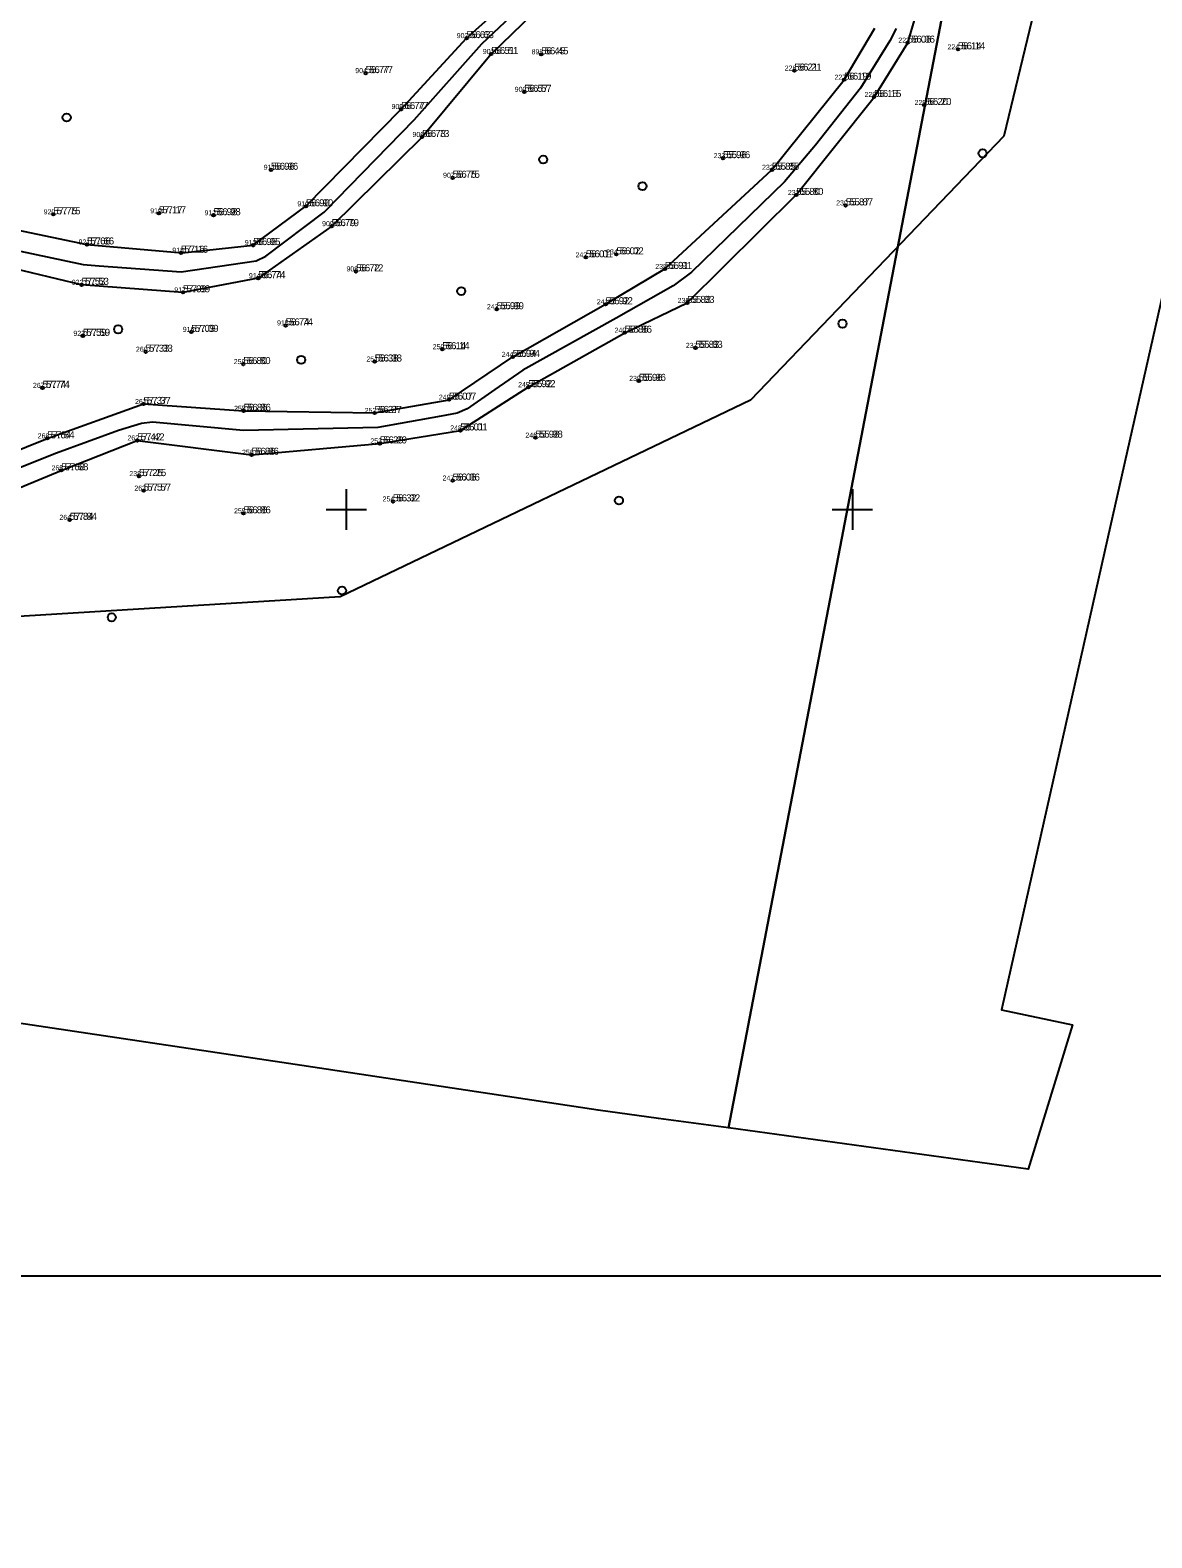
# Model space of a CAD drawing. Extents: x 554846 to 556995, y 6445875 to 6446723.
# Drawn here: x 555368.8 to 555479.6, y 6445948.4 to 6446097.4 of the extents above; entities that cross this region are included whole.
import ezdxf

# ---------------------------------------------------------------- set-up
doc = ezdxf.new("R2010")
doc.units = 0
for name, color, linetype in [('HALJASTUS', 7, 'Continuous'), ('KORGUS-EH2000', 7, 'Continuous'), ('MOOTKORG-EH2000', 7, 'Continuous'), ('MOOTMPUNKT', 7, 'Continuous'), ('MOOTNR', 7, 'Continuous'), ('MOOTPIIR', 7, 'Continuous'), ('PIIR', 7, 'Continuous'), ('TEE', 7, 'Continuous'), ('VORK', 7, 'Continuous'), ('VORMISTUS', 7, 'Continuous')]:
    doc.layers.add(name, color=color, linetype=linetype)

msp = doc.modelspace()

# ---------------------------------------------------------------- linework, layer by layer
at = {"layer": 'HALJASTUS'}
for centre in [(555372.37, 6446088.73), (555419.46, 6446084.58), (555462.87, 6446085.2), (555429.26, 6446081.95), (555411.36, 6446071.58), (555449.03, 6446068.37), (555377.46, 6446067.81), (555395.54, 6446064.79), (555426.94, 6446050.89), (555399.58, 6446041.99), (555376.83, 6446039.35)]:
    msp.add_circle(centre, 0.4, dxfattribs=at)
at = {"layer": 'KORGUS-EH2000'}
for centre in [(555411.89, 6446096.58), (555455.47, 6446096.13), (555460.43, 6446095.47), (555414.31, 6446095.01), (555419.26, 6446094.98), (555401.92, 6446093.12), (555444.27, 6446093.37), (555449.19, 6446092.47), (555417.59, 6446091.27), (555452.15, 6446090.76), (555405.42, 6446089.57), (555457.1, 6446089.97), (555407.49, 6446086.81), (555437.22, 6446084.72), (555392.56, 6446083.57), (555442.06, 6446083.57), (555410.51, 6446082.78), (555444.45, 6446081.08), (555371.05, 6446079.17), (555381.48, 6446079.27), (555386.88, 6446079.08), (555396.02, 6446079.96), (555449.35, 6446080.05), (555398.56, 6446078), (555374.38, 6446076.19), (555390.8, 6446076.13), (555383.66, 6446075.37), (555423.67, 6446074.92), (555426.69, 6446075.21), (555391.3, 6446072.86), (555400.97, 6446073.53), (555431.48, 6446073.77), (555373.85, 6446072.2), (555383.86, 6446071.46), (555414.86, 6446069.79), (555425.62, 6446070.28), (555433.69, 6446070.41), (555373.97, 6446067.16), (555384.69, 6446067.55), (555394.01, 6446068.19), (555427.51, 6446067.47), (555380.17, 6446065.59), (555409.49, 6446065.84), (555434.5, 6446065.97), (555389.83, 6446064.37), (555402.81, 6446064.62), (555416.44, 6446065.08), (555428.9, 6446062.71), (555369.99, 6446062.02), (555417.98, 6446062.09), (555379.96, 6446060.43), (555389.86, 6446059.75), (555389.86, 6446059.75), (555402.8, 6446059.54), (555410.15, 6446060.85), (555370.46, 6446057.03), (555379.35, 6446056.83), (555403.31, 6446056.53), (555411.27, 6446057.81), (555418.7, 6446057.1), (555390.65, 6446055.41), (555371.83, 6446053.87), (555379.52, 6446053.3), (555410.51, 6446052.86), (555379.99, 6446051.86), (555404.61, 6446050.8), (555372.68, 6446048.98), (555389.85, 6446049.62)]:
    msp.add_circle(centre, 0.125, dxfattribs=at)
at = {"layer": 'MOOTMPUNKT'}
for centre in [(555411.89, 6446096.58), (555455.47, 6446096.13), (555460.43, 6446095.47), (555414.31, 6446095.01), (555419.26, 6446094.98), (555401.92, 6446093.12), (555444.27, 6446093.37), (555449.19, 6446092.47), (555417.59, 6446091.27), (555452.15, 6446090.76), (555405.42, 6446089.57), (555457.1, 6446089.97), (555407.49, 6446086.81), (555437.22, 6446084.72), (555392.56, 6446083.57), (555442.06, 6446083.57), (555410.51, 6446082.78), (555444.45, 6446081.08), (555371.05, 6446079.17), (555381.48, 6446079.27), (555386.88, 6446079.08), (555396.02, 6446079.96), (555449.35, 6446080.05), (555398.56, 6446078), (555374.38, 6446076.19), (555390.8, 6446076.13), (555383.66, 6446075.37), (555423.67, 6446074.92), (555426.69, 6446075.21), (555391.3, 6446072.86), (555400.97, 6446073.53), (555431.48, 6446073.77), (555373.85, 6446072.2), (555383.86, 6446071.46), (555414.86, 6446069.79), (555425.62, 6446070.28), (555433.69, 6446070.41), (555373.97, 6446067.16), (555384.69, 6446067.55), (555394.01, 6446068.19), (555427.51, 6446067.47), (555380.17, 6446065.59), (555409.49, 6446065.84), (555434.5, 6446065.97), (555389.83, 6446064.37), (555402.81, 6446064.62), (555416.44, 6446065.08), (555428.9, 6446062.71), (555369.99, 6446062.02), (555417.98, 6446062.09), (555379.96, 6446060.43), (555389.86, 6446059.75), (555389.86, 6446059.75), (555402.8, 6446059.54), (555410.15, 6446060.85), (555370.46, 6446057.03), (555379.35, 6446056.83), (555403.31, 6446056.53), (555411.27, 6446057.81), (555418.7, 6446057.1), (555390.65, 6446055.41), (555371.83, 6446053.87), (555379.52, 6446053.3), (555410.51, 6446052.86), (555379.99, 6446051.86), (555404.61, 6446050.8), (555372.68, 6446048.98), (555389.85, 6446049.62)]:
    msp.add_circle(centre, 0.125, dxfattribs=at)
at = {"layer": 'MOOTPIIR'}
msp.add_lwpolyline([(555856.56, 6446356.05), (555752.84, 6446263.06), (555653.54, 6446239.26), (555594.53, 6446196.06), (555554.98, 6446185.17), (555476.19, 6446171.98), (555473.22, 6446121.18), (555464.98, 6446086.88), (555439.93, 6446060.82), (555399.38, 6446041.36), (555318.62, 6446036.42), (555233.24, 6446050.27)], dxfattribs=at)
at = {"layer": 'PIIR'}
msp.add_lwpolyline([(555848.15, 6446270.05), (555770.44, 6446257.1), (555601.76, 6446236.19), (555592.08, 6446205.8), (555590.17, 6446199.81), (555547.72, 6446198.88), (555471.93, 6446166.68), (555437.75, 6445988.89), (555430.84, 6445989.84), (555424.9, 6445990.66), (555394.94, 6445995.15), (555348.46, 6446002.11), (555303.97, 6446008.78), (555290.27, 6445950.91), (555289.66, 6445948.39), (555259.76, 6445985.47)], dxfattribs=at)
msp.add_lwpolyline([(555594.35, 6446199.31), (555580.72, 6446194.53), (555573.2, 6446192.45), (555562.73, 6446139.8), (555499.33, 6446154.09), (555491.55, 6446119.62), (555486.57, 6446097.52), (555481.82, 6446076.44), (555475.25, 6446047.27), (555464.73, 6446000.58), (555471.74, 6445999.08), (555467.38, 6445984.82), (555437.75, 6445988.89), (555471.93, 6446166.68), (555547.72, 6446198.88), (555590.17, 6446199.81)], close=True, dxfattribs=at)
at = {"layer": 'TEE'}
for points in [[(555256.61, 6446082.39), (555267.96, 6446080.12), (555279.72, 6446079.09), (555291.51, 6446080.24), (555300.12, 6446082.08), (555312.15, 6446084.79), (555319.08, 6446084.59), (555325.91, 6446083.6), (555336.42, 6446083), (555348.87, 6446084.02), (555357.05, 6446080.92), (555364.6, 6446078.23), (555374.38, 6446076.19), (555383.78, 6446075.37), (555390.8, 6446076.13), (555396.02, 6446079.96), (555405.42, 6446089.57), (555411.89, 6446096.58), (555419.56, 6446103.46)], [(555362.59, 6446050.02), (555371.83, 6446053.87), (555379.35, 6446056.83), (555390.65, 6446055.41), (555403.31, 6446056.53), (555411.27, 6446057.81), (555417.98, 6446062.09), (555427.51, 6446067.47), (555433.69, 6446070.41), (555444.45, 6446081.08), (555452.15, 6446090.76), (555455.47, 6446096.13), (555457.38, 6446102.63)], [(555419.45, 6446099.97), (555414.31, 6446095.01), (555407.49, 6446086.81), (555398.56, 6446078), (555391.3, 6446072.86), (555383.86, 6446071.46), (555373.85, 6446072.2), (555363.92, 6446074.58), (555356.22, 6446077.48), (555347.89, 6446080.29), (555336.39, 6446079.7), (555324.93, 6446080.84), (555318.7, 6446081.51), (555311.81, 6446081.32), (555301.28, 6446078.68), (555291.5, 6446076.78), (555279.92, 6446075.3), (555267.57, 6446076.5), (555255.14, 6446078.33)], [(555365.8, 6446075.96), (555374.01, 6446074.2), (555375.6, 6446074.08), (555383.67, 6446073.48), (555391.11, 6446074.58), (555392.06, 6446075.04), (555397.81, 6446079.38), (555406.7, 6446088.52), (555413.39, 6446096.01), (555418.56, 6446100.94)], [(555260.14, 6446058.52), (555267.45, 6446056.62), (555271.68, 6446055.36), (555278.75, 6446053.22), (555289.07, 6446052.56), (555303.18, 6446049.3), (555306.24, 6446048.9), (555313.8, 6446049.13), (555323.86, 6446049.99), (555333.31, 6446049.62), (555338.67, 6446048.65), (555345.24, 6446049.45), (555362.23, 6446053.72), (555370.46, 6446057.03), (555379.96, 6446060.43), (555389.86, 6446059.75), (555402.8, 6446059.54), (555410.15, 6446060.85), (555416.44, 6446065.08), (555425.62, 6446070.28), (555431.48, 6446073.77), (555442.06, 6446083.57), (555449.19, 6446092.47), (555452.21, 6446097.57)], [(555454.33, 6446097.54), (555453.69, 6446096.32), (555450.82, 6446091.64), (555446.37, 6446086.01), (555443.31, 6446082.39), (555434.12, 6446073.45), (555432.31, 6446072.09), (555426.65, 6446068.92), (555417.43, 6446063.76), (555414.68, 6446061.85), (555411.94, 6446059.95), (555410.95, 6446059.51), (555409.39, 6446059.23), (555403.11, 6446058.09), (555389.85, 6446057.81), (555380.85, 6446058.64), (555379.76, 6446058.5), (555377.48, 6446057.81), (555371.37, 6446055.57), (555362.89, 6446052.22)]]:
    msp.add_lwpolyline(points, dxfattribs=at)
at = {"layer": 'VORK'}
for p, q in [((555400, 6446052), (555400, 6446048)), ((555450, 6446052), (555450, 6446048)), ((555398, 6446050), (555402, 6446050)), ((555448, 6446050), (555452, 6446050))]:
    msp.add_line(p, q, dxfattribs=at)
at = {"layer": 'VORMISTUS'}
msp.add_lwpolyline([(555573.73, 6445974.27), (555573.73, 6446387.77), (554994.23, 6446387.77), (554994.23, 6445974.27), (555573.73, 6445974.27)], dxfattribs=at)

# ---------------------------------------------------------------- texts
at = {"layer": 'KORGUS-EH2000'}
for s, p in [('56.63', (555412.24, 6446096.58)), ('56.06', (555455.82, 6446096.13)), ('56.51', (555414.66, 6446095.01)), ('56.45', (555419.61, 6446094.98)), ('56.14', (555460.78, 6446095.47)), ('56.77', (555402.27, 6446093.12)), ('56.21', (555444.62, 6446093.37)), ('56.19', (555449.54, 6446092.47)), ('56.57', (555417.94, 6446091.27)), ('56.15', (555452.5, 6446090.76)), ('56.77', (555405.77, 6446089.57)), ('56.20', (555457.45, 6446089.97)), ('56.73', (555407.84, 6446086.81)), ('55.96', (555437.57, 6446084.72)), ('56.96', (555392.91, 6446083.57)), ('56.75', (555410.86, 6446082.78)), ('55.85', (555442.41, 6446083.57)), ('56.90', (555396.37, 6446079.96)), ('55.80', (555444.8, 6446081.08)), ('55.87', (555449.7, 6446080.05)), ('57.75', (555371.4, 6446079.17)), ('57.17', (555381.83, 6446079.27)), ('56.98', (555387.23, 6446079.08)), ('56.79', (555398.91, 6446078)), ('57.66', (555374.72, 6446076.19)), ('57.16', (555384.01, 6446075.37)), ('56.95', (555391.15, 6446076.13)), ('56.02', (555427.04, 6446075.21)), ('56.01', (555424.02, 6446074.92)), ('55.91', (555431.83, 6446073.77)), ('57.53', (555374.2, 6446072.2)), ('56.74', (555391.65, 6446072.86)), ('56.72', (555401.32, 6446073.53)), ('57.09', (555384.21, 6446071.46)), ('55.99', (555415.21, 6446069.79)), ('55.92', (555425.97, 6446070.28)), ('55.83', (555434.04, 6446070.41)), ('56.74', (555394.36, 6446068.19)), ('57.59', (555374.32, 6446067.16)), ('57.09', (555385.04, 6446067.55)), ('55.86', (555427.86, 6446067.47)), ('57.33', (555380.52, 6446065.59)), ('56.14', (555409.84, 6446065.84)), ('55.94', (555416.79, 6446065.08)), ('55.83', (555434.85, 6446065.97)), ('56.80', (555390.18, 6446064.37)), ('56.38', (555403.16, 6446064.62)), ('57.74', (555370.34, 6446062.02)), ('55.92', (555418.33, 6446062.09)), ('55.96', (555429.24, 6446062.71)), ('57.37', (555380.31, 6446060.43)), ('56.07', (555410.5, 6446060.85)), ('56.86', (555390.21, 6446059.75)), ('56.86', (555390.21, 6446059.75)), ('56.27', (555403.15, 6446059.54)), ('56.01', (555411.62, 6446057.81)), ('57.64', (555370.81, 6446057.03)), ('57.42', (555379.7, 6446056.83)), ('56.29', (555403.66, 6446056.53)), ('55.98', (555419.05, 6446057.1)), ('56.86', (555391, 6446055.41)), ('57.68', (555372.18, 6446053.87)), ('57.25', (555379.87, 6446053.3)), ('56.06', (555410.86, 6446052.86)), ('57.57', (555380.34, 6446051.86)), ('56.32', (555404.96, 6446050.8)), ('57.84', (555373.03, 6446048.98)), ('56.86', (555390.2, 6446049.62))]:
    msp.add_text(s, height=0.7, dxfattribs=at).set_placement(p)
at = {"layer": 'MOOTKORG-EH2000'}
for s, p in [('56.63', (555411.89, 6446096.58)), ('56.06', (555455.47, 6446096.13)), ('56.51', (555414.31, 6446095.01)), ('56.45', (555419.26, 6446094.98)), ('56.14', (555460.43, 6446095.47)), ('56.77', (555401.92, 6446093.12)), ('56.21', (555444.27, 6446093.37)), ('56.19', (555449.19, 6446092.47)), ('56.57', (555417.59, 6446091.27)), ('56.15', (555452.15, 6446090.76)), ('56.77', (555405.42, 6446089.57)), ('56.20', (555457.1, 6446089.97)), ('56.73', (555407.49, 6446086.81)), ('55.96', (555437.22, 6446084.72)), ('56.96', (555392.56, 6446083.57)), ('56.75', (555410.51, 6446082.78)), ('55.85', (555442.06, 6446083.57)), ('56.90', (555396.02, 6446079.96)), ('55.80', (555444.45, 6446081.08)), ('55.87', (555449.35, 6446080.05)), ('57.75', (555371.05, 6446079.17)), ('57.17', (555381.48, 6446079.27)), ('56.98', (555386.88, 6446079.08)), ('56.79', (555398.56, 6446078)), ('57.66', (555374.38, 6446076.19)), ('57.16', (555383.66, 6446075.37)), ('56.95', (555390.8, 6446076.13)), ('56.02', (555426.69, 6446075.21)), ('56.01', (555423.67, 6446074.92)), ('55.91', (555431.48, 6446073.77)), ('57.53', (555373.85, 6446072.2)), ('56.74', (555391.3, 6446072.86)), ('56.72', (555400.97, 6446073.53)), ('57.09', (555383.86, 6446071.46)), ('55.99', (555414.86, 6446069.79)), ('55.92', (555425.62, 6446070.28)), ('55.83', (555433.69, 6446070.41)), ('56.74', (555394.01, 6446068.19)), ('57.59', (555373.97, 6446067.16)), ('57.09', (555384.69, 6446067.55)), ('55.86', (555427.51, 6446067.47)), ('57.33', (555380.17, 6446065.59)), ('56.14', (555409.49, 6446065.84)), ('55.94', (555416.44, 6446065.08)), ('55.83', (555434.5, 6446065.97)), ('56.80', (555389.83, 6446064.37)), ('56.38', (555402.81, 6446064.62)), ('57.74', (555369.99, 6446062.02)), ('55.92', (555417.98, 6446062.09)), ('55.96', (555428.9, 6446062.71)), ('57.37', (555379.96, 6446060.43)), ('56.07', (555410.15, 6446060.85)), ('56.86', (555389.86, 6446059.75)), ('56.86', (555389.86, 6446059.75)), ('56.27', (555402.8, 6446059.54)), ('56.01', (555411.27, 6446057.81)), ('57.64', (555370.46, 6446057.03)), ('57.42', (555379.35, 6446056.83)), ('56.29', (555403.31, 6446056.53)), ('55.98', (555418.7, 6446057.1)), ('56.86', (555390.65, 6446055.41)), ('57.68', (555371.83, 6446053.87)), ('57.25', (555379.52, 6446053.3)), ('56.06', (555410.51, 6446052.86)), ('57.57', (555379.99, 6446051.86)), ('56.32', (555404.61, 6446050.8)), ('57.84', (555372.68, 6446048.98)), ('56.86', (555389.85, 6446049.62))]:
    msp.add_text(s, height=0.7, dxfattribs=at).set_placement(p)
at = {"layer": 'MOOTNR'}
for s, p in [('902', (555410.91, 6446096.58)), ('901', (555413.49, 6446095.01)), ('895', (555418.31, 6446094.98)), ('223', (555454.54, 6446096.13)), ('224', (555459.4, 6446095.47)), ('226', (555443.32, 6446093.37)), ('904', (555400.89, 6446093.12)), ('227', (555448.24, 6446092.47)), ('900', (555416.64, 6446091.27)), ('228', (555451.2, 6446090.76)), ('905', (555404.47, 6446089.57)), ('229', (555456.15, 6446089.97)), ('906', (555406.54, 6446086.81)), ('233', (555436.3, 6446084.72)), ('911', (555391.84, 6446083.57)), ('232', (555441.08, 6446083.57)), ('907', (555409.56, 6446082.78)), ('910', (555395.17, 6446079.96)), ('231', (555443.63, 6446081.08)), ('230', (555448.4, 6446080.05)), ('920', (555370.1, 6446079.17)), ('919', (555380.63, 6446079.27)), ('912', (555386, 6446079.08)), ('909', (555397.61, 6446078)), ('921', (555373.55, 6446076.19)), ('913', (555389.97, 6446076.13)), ('918', (555382.81, 6446075.37)), ('242', (555422.65, 6446074.92)), ('234', (555425.67, 6446075.21)), ('914', (555390.38, 6446072.86)), ('908', (555400.02, 6446073.53)), ('235', (555430.53, 6446073.77)), ('922', (555372.88, 6446072.2)), ('917', (555383.01, 6446071.46)), ('243', (555413.89, 6446069.79)), ('241', (555424.75, 6446070.28)), ('236', (555432.74, 6446070.41)), ('5', (555433.5, 6446070.34)), ('915', (555393.16, 6446068.19)), ('923', (555373.04, 6446067.16)), ('916', (555383.84, 6446067.55)), ('240', (555426.51, 6446067.47)), ('260', (555379.22, 6446065.59)), ('250', (555408.54, 6446065.84)), ('244', (555415.36, 6446065.08)), ('237', (555433.55, 6446065.97)), ('259', (555388.88, 6446064.37)), ('251', (555401.99, 6446064.62)), ('267', (555369.04, 6446062.02)), ('245', (555416.98, 6446062.09)), ('239', (555427.95, 6446062.71)), ('249', (555409.15, 6446060.85)), ('261', (555379.13, 6446060.43)), ('258', (555388.91, 6446059.75)), ('257', (555388.92, 6446059.75)), ('252', (555401.82, 6446059.54)), ('248', (555410.27, 6446057.81)), ('266', (555369.51, 6446057.03)), ('262', (555378.38, 6446056.83)), ('253', (555402.38, 6446056.53)), ('246', (555417.7, 6446057.1)), ('256', (555389.7, 6446055.41)), ('265', (555370.88, 6446053.87)), ('238', (555378.57, 6446053.3)), ('263', (555379.06, 6446051.86)), ('247', (555409.51, 6446052.86)), ('254', (555403.59, 6446050.8)), ('264', (555371.66, 6446048.98)), ('255', (555388.91, 6446049.62))]:
    msp.add_text(s, height=0.5, dxfattribs=at).set_placement(p)

doc.saveas('drawing.dxf')
